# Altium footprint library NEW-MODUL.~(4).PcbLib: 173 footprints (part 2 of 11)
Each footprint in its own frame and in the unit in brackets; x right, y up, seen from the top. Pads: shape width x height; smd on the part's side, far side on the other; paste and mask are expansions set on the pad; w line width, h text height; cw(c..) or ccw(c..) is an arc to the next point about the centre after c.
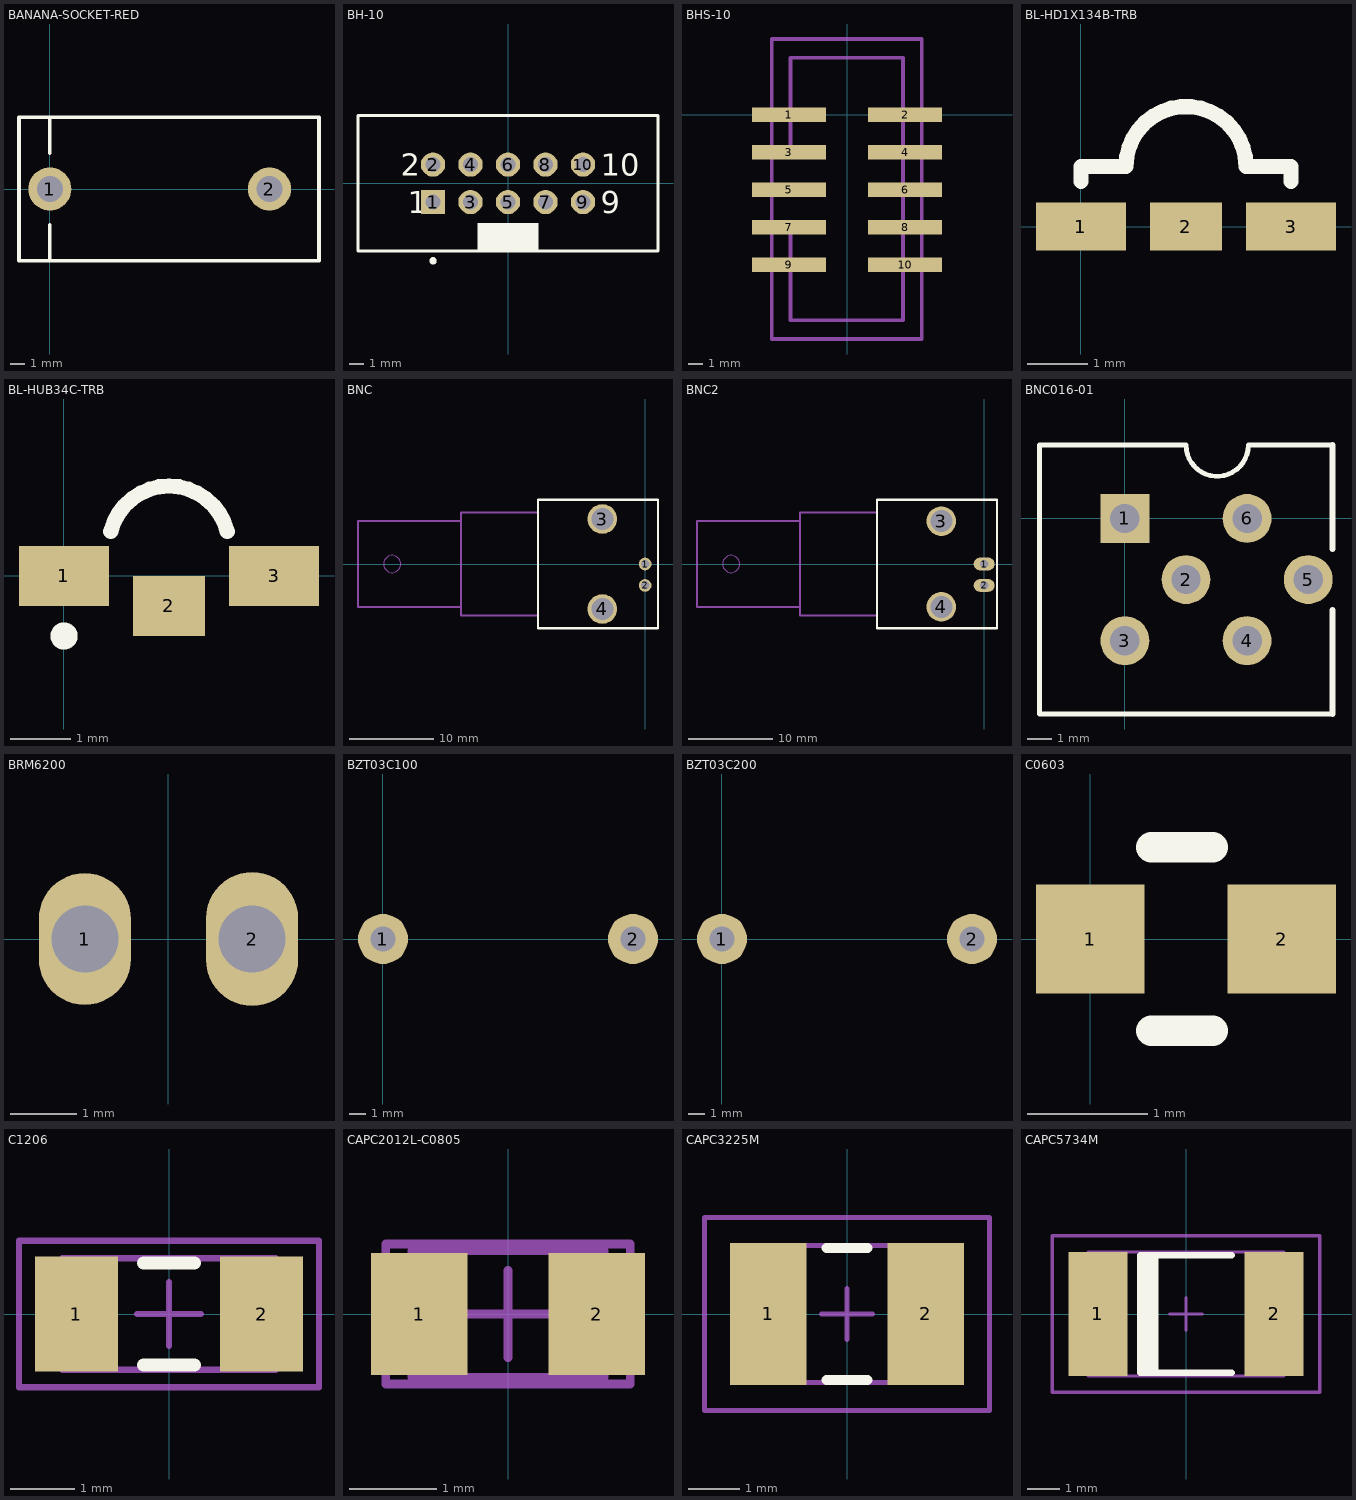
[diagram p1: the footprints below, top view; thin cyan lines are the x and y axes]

## BANANA-SOCKET-RED [mm]
pads (2):
  round 3 hole 1.8: 1(0,0) 2(15.3,0)
Top Overlay:
  lines w0.254: 0,-5 0,-2.5 ; 0,2.5 0,5 ; -2.15,-5 -2.15,5 18.75,5 18.75,-5 -2.15,-5
3D body "deltron-571-0500-4mm-90deg-single-socket-data.STEP": height 12.4, standoff -5.5, extent -4.675,-5.461 18.695,4.889

## BH-10 [mm] "Connector; IDC, Low Profile Male Header, Thru-Hole; 10 Position; Vertical; Pitch 2.54 mm; Body 20.32 x 9.2 x 9.45 mm (LxWxH)"
height 9.45
pads (10):
  rect 1.65x1.65 hole 1: 1(-5.08,-1.27)
  round 1.65 hole 1: 2(-5.08,1.27) 3(-2.54,-1.27) 4(-2.54,1.27) 5(0,-1.27) 6(0,1.27) 7(2.54,-1.27) 8(2.54,1.27) 9(5.08,-1.27) 10(5.08,1.27)
Top Overlay:
  circle w0.25: c-5.08,-5.25 r0.125
  rectangle: -2.05,-4.6 2.05,-2.7
  lines w0.2: -10.16,-4.6 -10.16,4.6 10.16,4.6 10.16,-4.6 -10.16,-4.6
  text "2" at -7.28,0.52 h1.5
  text "1" at -6.78,-2.02 h1.5
  text "10" at 6.28,0.52 h1.5
  text "9" at 6.28,-2.02 h1.5
Mechanical 13:
  lines w0.1: -10.16,-4.6 10.16,-4.6 10.16,4.6 -10.16,4.6 -10.16,-4.6
3D body "User Library-IDC-10M.STEP": height 9.3, standoff -3.1, extent -10.15,-4.4 10.15,4.7

## BHS-10 [mm]
pads (10):
  rect 5x1 smd: 1(-3.937,0) 2(3.937,0) 3(-3.937,-2.54) 4(3.937,-2.54) 5(-3.937,-5.08) 6(3.937,-5.08) 7(-3.937,-7.62) 8(3.937,-7.62) 9(-3.937,-10.16) 10(3.937,-10.16)
Mechanical 1:
  lines w0.254: -5.105,-7.57 -3.835,-7.57 -3.835,-13.92 3.785,-13.92 3.785,3.86 -3.835,3.86 -3.835,-2.49 ; -5.08,-2.565 -3.81,-2.565 ; -5.105,-15.19 5.055,-15.19 5.055,5.13 -5.105,5.13 -5.105,-15.19
3D body "header_awhw10g-smd.stp": height 10.66, standoff 0.02, extent -4.75,-15.24 4.75,5.08

## BL-HD1X134B-TRB [mm]
pads (3):
  rect 1.5x0.8 smd: 1(0,0) 3(3.5,0)
  rect 1.2x0.8 smd: 2(1.75,0)
Top Overlay:
  lines w0.254: 0,0.75 0,1 0.75,1 cw(c1.75,1) 2.75,1 3.5,1 3.5,0.75
3D body "User Library-APA3010GCCK_RED.step": height 1, standoff 0.01, extent 0.25,-0.05 3.25,1.95

## BL-HUB34C-TRB [mm]
pads (3):
  rect 1.5x1 smd: 1(0,0) 3(3.5,0)
  rect 1.2x1 smd: 2(1.75,-0.5)
Top Overlay:
  circle w0.254: c0,-1 r0.1
  lines w0.254: 0.78,0.743 cw(c1.75,0.5) 2.72,0.743
3D body "User Library-APA3010GCCK_RED.step": height 1, standoff 0.01, extent 0.25,-0.5 3.25,1.5

## BNC [mm]
pads (4):
  round 1.5 hole 1 unplated: 1(0,0) 2(0,-2.54)
  round 3.5 hole 2.6 unplated: 3(-5.08,5.334) 4(-5.08,-5.334)
Top Overlay:
  lines w0.254: -12.7,-7.62 -12.7,7.62 1.524,7.62 1.524,-7.62 -12.7,-7.62
Mechanical 1:
  circle w0.025: c-29.972,0 r1.016
  lines w0.254: -21.844,-5.08 -34.036,-5.08 -34.036,5.08 -21.844,5.08 ; -12.7,-6.096 -21.844,-6.096 -21.844,6.096 -12.7,6.096
3D body "User Library-m0000780.step": height 15.37, standoff -4.11, extent -32.95,-7.379 2.102,7.379

## BNC2 [mm]
pads (4):
  oval 2.5x1.5 hole 1 unplated: 1(0,0) 2(0,-2.54)
  round 3.5 hole 2.6 unplated: 3(-5.08,5.08) 4(-5.08,-5.08)
Top Overlay:
  lines w0.254: -12.7,-7.62 1.524,-7.62 1.524,7.62 -12.7,7.62 -12.7,-7.62
Mechanical 1:
  circle w0.025: c-29.972,0 r1.016
  lines w0.254: -21.844,-5.08 -34.036,-5.08 -34.036,5.08 -21.844,5.08 ; -12.7,-6.096 -21.844,-6.096 -21.844,6.096 -12.7,6.096
3D body "User Library-m0000780.step": height 15.37, standoff -4.11, extent -32.95,-7.379 2.102,7.379

## BNC016-01 [mm] "Low profile version"
height 8
pads (6):
  rect 2x2 hole 1.2: 1(0,0)
  round 2 hole 1.2: 2(2.5,-2.5) 3(0,-5) 4(5,-5) 5(7.5,-2.5) 6(5,0)
Top Overlay:
  lines w0.2: 8.5,-8 -3.5,-8 -3.5,3 2,3 2.5,3 ccw(c3.775,3) 5.05,3 5.5,3 8.5,3
  lines w0.254: 8.5,-8 8.5,-3.75 ; 8.5,-1.25 8.5,3
3D body "User Library-BNX003.step": height 13.02, standoff -2.48, extent -3.5,-8 8.5,3

## BRM6200 [mm]
pads (2):
  oval 1.4x2 hole 1.016: 1(-1.27,0)
  oval 1.4x2.032 hole 1.016: 2(1.27,0)
3D body "User Library-LG2040_right angle.step": height 4.99, standoff -4, extent -1.959,-0.325 1.545,10.125

## BZT03C100 [mm]
pads (2):
  round 3 hole 1.5 unplated: 1(0,0) 2(15,0)
3D body "User Library-BYV28-200.step": height 6, standoff -1.25, extent -0.675,-2.25 15.675,2.25

## BZT03C200 [mm]
pads (2):
  round 3 hole 1.5 unplated: 1(0,0) 2(15,0)
3D body "User Library-BYV28-200.step": height 6, standoff -1.25, extent -0.675,-2.25 15.675,2.25

## C0603 [mm]
pads (2):
  rect 0.9x0.9 smd: 1(0,0) 2(1.587,0)
Top Overlay:
  lines w0.254: 0.508,-0.762 1.016,-0.762 ; 0.508,0.762 1.016,0.762
3D body "User Library-0603 SMD Capacitor.step": height 0.3, standoff 0, extent -0.038,-0.4 1.562,0.4

## C1206 [mm] "C1206"
pads (2):
  rect 1.3x1.8 smd: 1(-1.45,0) 2(1.45,0)
Top Overlay:
  lines w0.2: -0.4,-0.8 0.4,-0.8 ; -0.4,0.8 0.4,0.8
Mechanical 13:
  lines w0.1: -1.675,-0.875 1.675,-0.875 1.675,0.875 -1.675,0.875 -1.675,-0.875
Mechanical 15:
  lines w0.1: -0.5,0 0.5,0 ; 0,-0.5 0,0.5 ; -2.35,-1.15 2.35,-1.15 2.35,1.15 -2.35,1.15 -2.35,-1.15
3D body "User Library-1206 SMD Capacitor.step": height 1, standoff 0, extent -1.6,-0.8 1.6,0.8
3D body "User Library-1206 SMD Capacitor.step": height 1, standoff 0, extent -1.6,-0.8 1.6,0.8

## CAPC2012L-С0805 [mm] "Chip Capacitor, Body 2.0x1.3mm, IPC High Density"
height 1.1
pads (2):
  rect 1.1x1.4 smd: 1(-1.016,0) 2(1.016,0)
Mechanical 13:
  lines w0.1: -1.1,-0.725 1.1,-0.725 1.1,0.725 -1.1,0.725 -1.1,-0.725
Mechanical 15:
  lines w0.1: -0.5,0 0.5,0 ; 0,-0.5 0,0.5 ; -1.4,-0.8 1.4,-0.8 1.4,0.8 -1.4,0.8 -1.4,-0.8
3D body "User Library-0805 SMD Capacitor.step": height 0.78, standoff 0, extent -1,-0.625 1,0.625

## CAPC3225M [mm] "Chip Capacitor, Body 3.2x2.5mm, IPC Low Density"
height 1.35
pads (2):
  rect 1.5x2.8 smd: 1(-1.55,0) 2(1.55,0)
Top Overlay:
  lines w0.2: -0.4,-1.3 0.4,-1.3 ; -0.4,1.3 0.4,1.3
Mechanical 13:
  lines w0.1: -1.7,-1.35 1.7,-1.35 1.7,1.35 -1.7,1.35 -1.7,-1.35
Mechanical 15:
  lines w0.1: -0.5,0 0.5,0 ; 0,-0.5 0,0.5 ; -2.8,-1.9 2.8,-1.9 2.8,1.9 -2.8,1.9 -2.8,-1.9
3D body "User Library-Solid Tantalum Chip Capacitor.step": height 2.11, standoff -0.04, extent -2.499,-1.473 2.499,1.524

## CAPC5734M [mm] "Chip Capacitor, Body 5.7x3.4mm, IPC Low Density"
height 2.16
pads (2):
  rect 1.8x3.8 smd: 1(-2.7,0) 2(2.7,0)
Top Overlay:
  rectangle: -1.4,-1.8 -0.85,1.8
  lines w0.2: 1.4,-1.8 -1.4,-1.8 -1.4,1.8 1.4,1.8
Mechanical 13:
  lines w0.1: -3,-1.9 3,-1.9 3,1.9 -3,1.9 -3,-1.9
Mechanical 15:
  lines w0.1: -0.5,0 0.5,0 ; 0,-0.5 0,0.5 ; -4.1,-2.4 4.1,-2.4 4.1,2.4 -4.1,2.4 -4.1,-2.4
3D body "User Library-Tantalum Size C.step": height 2.6, standoff 0, extent -2.9,-1.6 2.9,1.6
